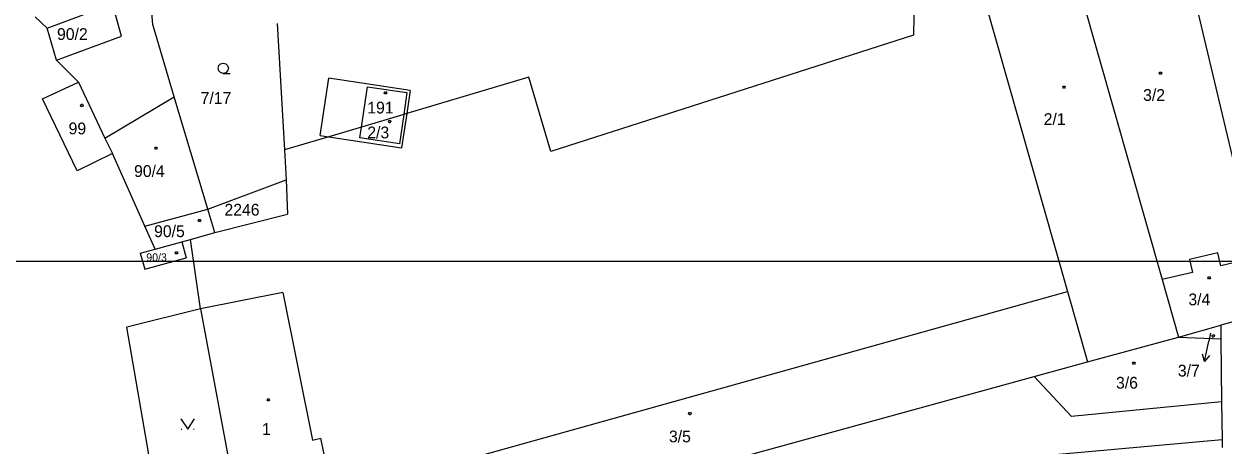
# Model space of a CAD drawing. Extents: x -802857 to -799647, y -1020285 to -1015884.
# Drawn here: x -801490 to -801316.9, y -1017640.2 to -1017579.5 of the extents above; entities that cross this region are included whole.
import ezdxf

# ---------------------------------------------------------------- set-up
doc = ezdxf.new("R2010")
doc.units = 0
for name, color, linetype in [('Default', 7, 'Continuous'), ('KN_HRANICE', 7, 'Continuous'), ('KN_KULTURY', 7, 'Continuous'), ('KN_PARCELY', 7, 'Continuous'), ('KN_SLUCKY', 7, 'Continuous'), ('LEGENDA', 7, 'Continuous')]:
    doc.layers.add(name, color=color, linetype=linetype)

# ---------------------------------------------------------------- blocks, each defined once
blk = doc.blocks.new('304')
at = {"layer": 'Default'}
blk.add_lwpolyline([(0, 0), (-0.38, 0.1), (-0.65, 0.37), (-0.75, 0.74), (-0.65, 1.11), (-0.38, 1.38), (-0.01, 1.48), (0.36, 1.38), (0.63, 1.11), (0.73, 0.73), (0.63, 0.35), (0.36, 0.08), (-0.02, -0.02), (0.98, -0.02)], dxfattribs=at)
blk = doc.blocks.new('314')
at = {"layer": 'Default'}
for p, q in [((-0.95, 0), (-0.85, 0)), ((0.85, 0), (0.95, 0))]:
    blk.add_line(p, q, dxfattribs=at)
blk.add_lwpolyline([(-1, 1.5), (0, 0), (1, 1.5)], dxfattribs=at)
blk = doc.blocks.new('NAHRADNI_SYMBOL')
at = {"layer": 'Default'}
blk.add_lwpolyline([(0.09, 0.15), (0.18, 0), (0.09, -0.15), (-0.09, -0.15), (-0.18, 0), (-0.09, 0.15), (0.09, 0.15)], dxfattribs=at)
blk = doc.blocks.new('10292')
at = {"layer": 'Default'}
blk.add_line((0, 3), (0, 0), dxfattribs=at)
blk.add_lwpolyline([(-0.5, 2), (0, 3), (0.5, 2)], dxfattribs=at)
blk = doc.blocks.new('402')
at = {"layer": 'Default'}
blk.add_lwpolyline([(0.09, 0.15), (0.18, 0), (0.09, -0.15), (-0.09, -0.15), (-0.18, 0), (-0.09, 0.15), (0.09, 0.15)], dxfattribs=at)

msp = doc.modelspace()

# ---------------------------------------------------------------- linework, layer by layer
at = {"layer": 'KN_HRANICE'}
for p, q in [((-801343.82, -1017553), (-801325.84, -1017616.37)), ((-801361.51, -1017570.05), (-801361.71, -1017581.12)), ((-801471.38, -1017579.57), (-801471.83, -1017574.62)), ((-801486.65, -1017580.08), (-801477.2, -1017576.6)), ((-801314.53, -1017603.45), (-801320.87, -1017576.78)), ((-801486.65, -1017580.08), (-801488.39, -1017578.43)), ((-801485.28, -1017584.71), (-801486.65, -1017580.08)), ((-801468.32, -1017590), (-801471.38, -1017579.57)), ((-801453.46, -1017579.4), (-801452.43, -1017597.66)), ((-801361.71, -1017581.12), (-801413.99, -1017597.89)), ((-801482.14, -1017587.87), (-801485.28, -1017584.71)), ((-801447.25, -1017595.56), (-801446, -1017587.3)), ((-801434.27, -1017589.08), (-801446, -1017587.3)), ((-801417.15, -1017587.18), (-801434.77, -1017592.42)), ((-801413.99, -1017597.89), (-801417.15, -1017587.18)), ((-801487.31, -1017590.29), (-801482.14, -1017587.87)), ((-801482.14, -1017587.87), (-801478.31, -1017595.94)), ((-801434.27, -1017589.08), (-801434.77, -1017592.42)), ((-801482.34, -1017600.68), (-801487.31, -1017590.29)), ((-801478.31, -1017595.94), (-801468.32, -1017590)), ((-801463.49, -1017606.2), (-801468.32, -1017590)), ((-801435.2, -1017592.55), (-801441.33, -1017594.37)), ((-801434.77, -1017592.42), (-801435.52, -1017597.34)), ((-801434.77, -1017592.42), (-801435.2, -1017592.55)), ((-801441.33, -1017594.37), (-801446, -1017595.75)), ((-801478.31, -1017595.94), (-801477.24, -1017598.19)), ((-801446, -1017595.75), (-801452.43, -1017597.66)), ((-801447.25, -1017595.56), (-801446, -1017595.75)), ((-801446, -1017595.75), (-801435.52, -1017597.34)), ((-801452.43, -1017597.66), (-801452.19, -1017601.97)), ((-801477.24, -1017598.19), (-801482.34, -1017600.68)), ((-801472.58, -1017608.66), (-801477.24, -1017598.19)), ((-801463.49, -1017606.2), (-801452.19, -1017601.97)), ((-801452.19, -1017601.97), (-801452, -1017606.94)), ((-801472.58, -1017608.66), (-801463.49, -1017606.2)), ((-801462.47, -1017609.6), (-801463.49, -1017606.2)), ((-801462.47, -1017609.6), (-801452, -1017606.94)), ((-801471.09, -1017611.99), (-801472.58, -1017608.66)), ((-801465.96, -1017610.57), (-801462.47, -1017609.6)), ((-801471.09, -1017611.99), (-801467.24, -1017610.92)), ((-801467.24, -1017610.92), (-801465.96, -1017610.57)), ((-801467.24, -1017610.92), (-801466.59, -1017613.23)), ((-801464.55, -1017620.59), (-801465.96, -1017610.57)), ((-801473.21, -1017612.58), (-801471.09, -1017611.99)), ((-801473.21, -1017612.58), (-801472.57, -1017614.89)), ((-801472.57, -1017614.89), (-801466.59, -1017613.23)), ((-801317.78, -1017612.5), (-801321.88, -1017613.46)), ((-801321.88, -1017613.46), (-801321.44, -1017615.34)), ((-801317.34, -1017614.38), (-801317.78, -1017612.5)), ((-801315.54, -1017613.96), (-801317.34, -1017614.38)), ((-801321.44, -1017615.34), (-801325.84, -1017616.37)), ((-801325.84, -1017616.37), (-801323.48, -1017624.68)), ((-801452.63, -1017618.23), (-801464.55, -1017620.59)), ((-801452.63, -1017618.23), (-801448.35, -1017639.53)), ((-801439.56, -1017646.05), (-801339.49, -1017618.1)), ((-801339.49, -1017618.1), (-801336.61, -1017628.26)), ((-801464.55, -1017620.59), (-801475.13, -1017623.23)), ((-801464.55, -1017620.59), (-801460.47, -1017642.27)), ((-801313.67, -1017621.93), (-801317.37, -1017622.97)), ((-801469.47, -1017656.08), (-801475.13, -1017623.23)), ((-801323.48, -1017624.68), (-801317.37, -1017622.97)), ((-801317.37, -1017622.97), (-801317.35, -1017624.91)), ((-801336.61, -1017628.26), (-801323.48, -1017624.68)), ((-801323.48, -1017624.68), (-801317.35, -1017624.91)), ((-801317.35, -1017624.91), (-801317.25, -1017634.01)), ((-801344.28, -1017630.37), (-801336.61, -1017628.26)), ((-801436.88, -1017655.78), (-801344.28, -1017630.37)), ((-801338.92, -1017636.13), (-801344.28, -1017630.37)), ((-801317.25, -1017634.01), (-801338.92, -1017636.13)), ((-801317.25, -1017634.01), (-801317.19, -1017639.44)), ((-801448.35, -1017639.53), (-801447.15, -1017639.26)), ((-801445.17, -1017648.98), (-801447.15, -1017639.26)), ((-801347.72, -1017642.2), (-801317.19, -1017639.44)), ((-801317.19, -1017639.44), (-801317.18, -1017640.62))]:
    msp.add_line(p, q, dxfattribs=at)
at = {"layer": 'KN_PARCELY'}
msp.add_line((-801318.83, -1017624.08), (-801319.08, -1017625.26), dxfattribs=at)
at = {"layer": 'KN_SLUCKY'}
for p, q in [((-801356.95, -1017556.58), (-801339.49, -1017618.1)), ((-801475.91, -1017581.24), (-801477.2, -1017576.6)), ((-801485.28, -1017584.71), (-801475.91, -1017581.24)), ((-801441.33, -1017594.37), (-801440.42, -1017588.56)), ((-801440.42, -1017588.56), (-801434.75, -1017589.39)), ((-801434.75, -1017589.39), (-801435.2, -1017592.55)), ((-801435.2, -1017592.55), (-801435.81, -1017596.76)), ((-801441.57, -1017595.93), (-801441.33, -1017594.37)), ((-801435.81, -1017596.76), (-801441.57, -1017595.93))]:
    msp.add_line(p, q, dxfattribs=at)
at = {"layer": 'LEGENDA'}
msp.add_lwpolyline([(-801703.84, -1017613.71), (-800862.84, -1017613.71), (-800862.84, -1017019.71), (-801703.84, -1017019.71)], close=True, dxfattribs=at)

# ---------------------------------------------------------------- block references
at = {"layer": 'KN_KULTURY'}
for name, p in [('304', (-801461.24, -1017586.61)), ('NAHRADNI_SYMBOL', (-801326.07, -1017586.6)), ('402', (-801339.98, -1017588.59)), ('402', (-801437.84, -1017589.42)), ('402', (-801481.65, -1017591.23)), ('402', (-801437.24, -1017593.58)), ('NAHRADNI_SYMBOL', (-801470.94, -1017597.4)), ('NAHRADNI_SYMBOL', (-801464.68, -1017607.84)), ('NAHRADNI_SYMBOL', (-801467.99, -1017612.51)), ('402', (-801319.04, -1017616.11)), ('NAHRADNI_SYMBOL', (-801318.45, -1017624.51)), ('NAHRADNI_SYMBOL', (-801329.92, -1017628.44)), ('402', (-801454.74, -1017633.73)), ('402', (-801393.95, -1017635.72)), ('314', (-801466.37, -1017637.95))]:
    msp.add_blockref(name, p, dxfattribs=at)
at = {"layer": 'KN_PARCELY', "rotation": 168.048521}
msp.add_blockref('10292', (-801319.08, -1017625.26), dxfattribs=at)

# ---------------------------------------------------------------- texts
at = {"layer": 'KN_PARCELY'}
for s, height, p in [('90/2', 1.7, (-801485.22, -1017581.79)), ('7/17', 1.7, (-801464.51, -1017591.02)), ('3/2', 1.7, (-801328.57, -1017590.58)), ('191', 1.7, (-801440.47, -1017592.4)), ('2/1', 1.7, (-801342.91, -1017594.06)), ('99', 1.7, (-801483.55, -1017595.41)), ('2/3', 1.7, (-801440.47, -1017595.99)), ('90/4', 1.7, (-801474.11, -1017601.56)), ('2246', 1.7, (-801461.07, -1017607.14)), ('90/5', 1.7, (-801471.22, -1017610.24)), ('90/3', 1.14, (-801472.35, -1017613.73)), ('3/4', 1.7, (-801322.04, -1017620.08)), ('3/7', 0.1, (-801318.98, -1017624.08)), ('3/7', 1.7, (-801323.56, -1017630.36)), ('3/6', 1.7, (-801332.48, -1017632.11)), ('1', 1.7, (-801455.66, -1017638.79)), ('3/5', 1.7, (-801396.96, -1017639.86))]:
    msp.add_text(s, height=height, dxfattribs=at).set_placement(p)

doc.saveas('drawing.dxf')
